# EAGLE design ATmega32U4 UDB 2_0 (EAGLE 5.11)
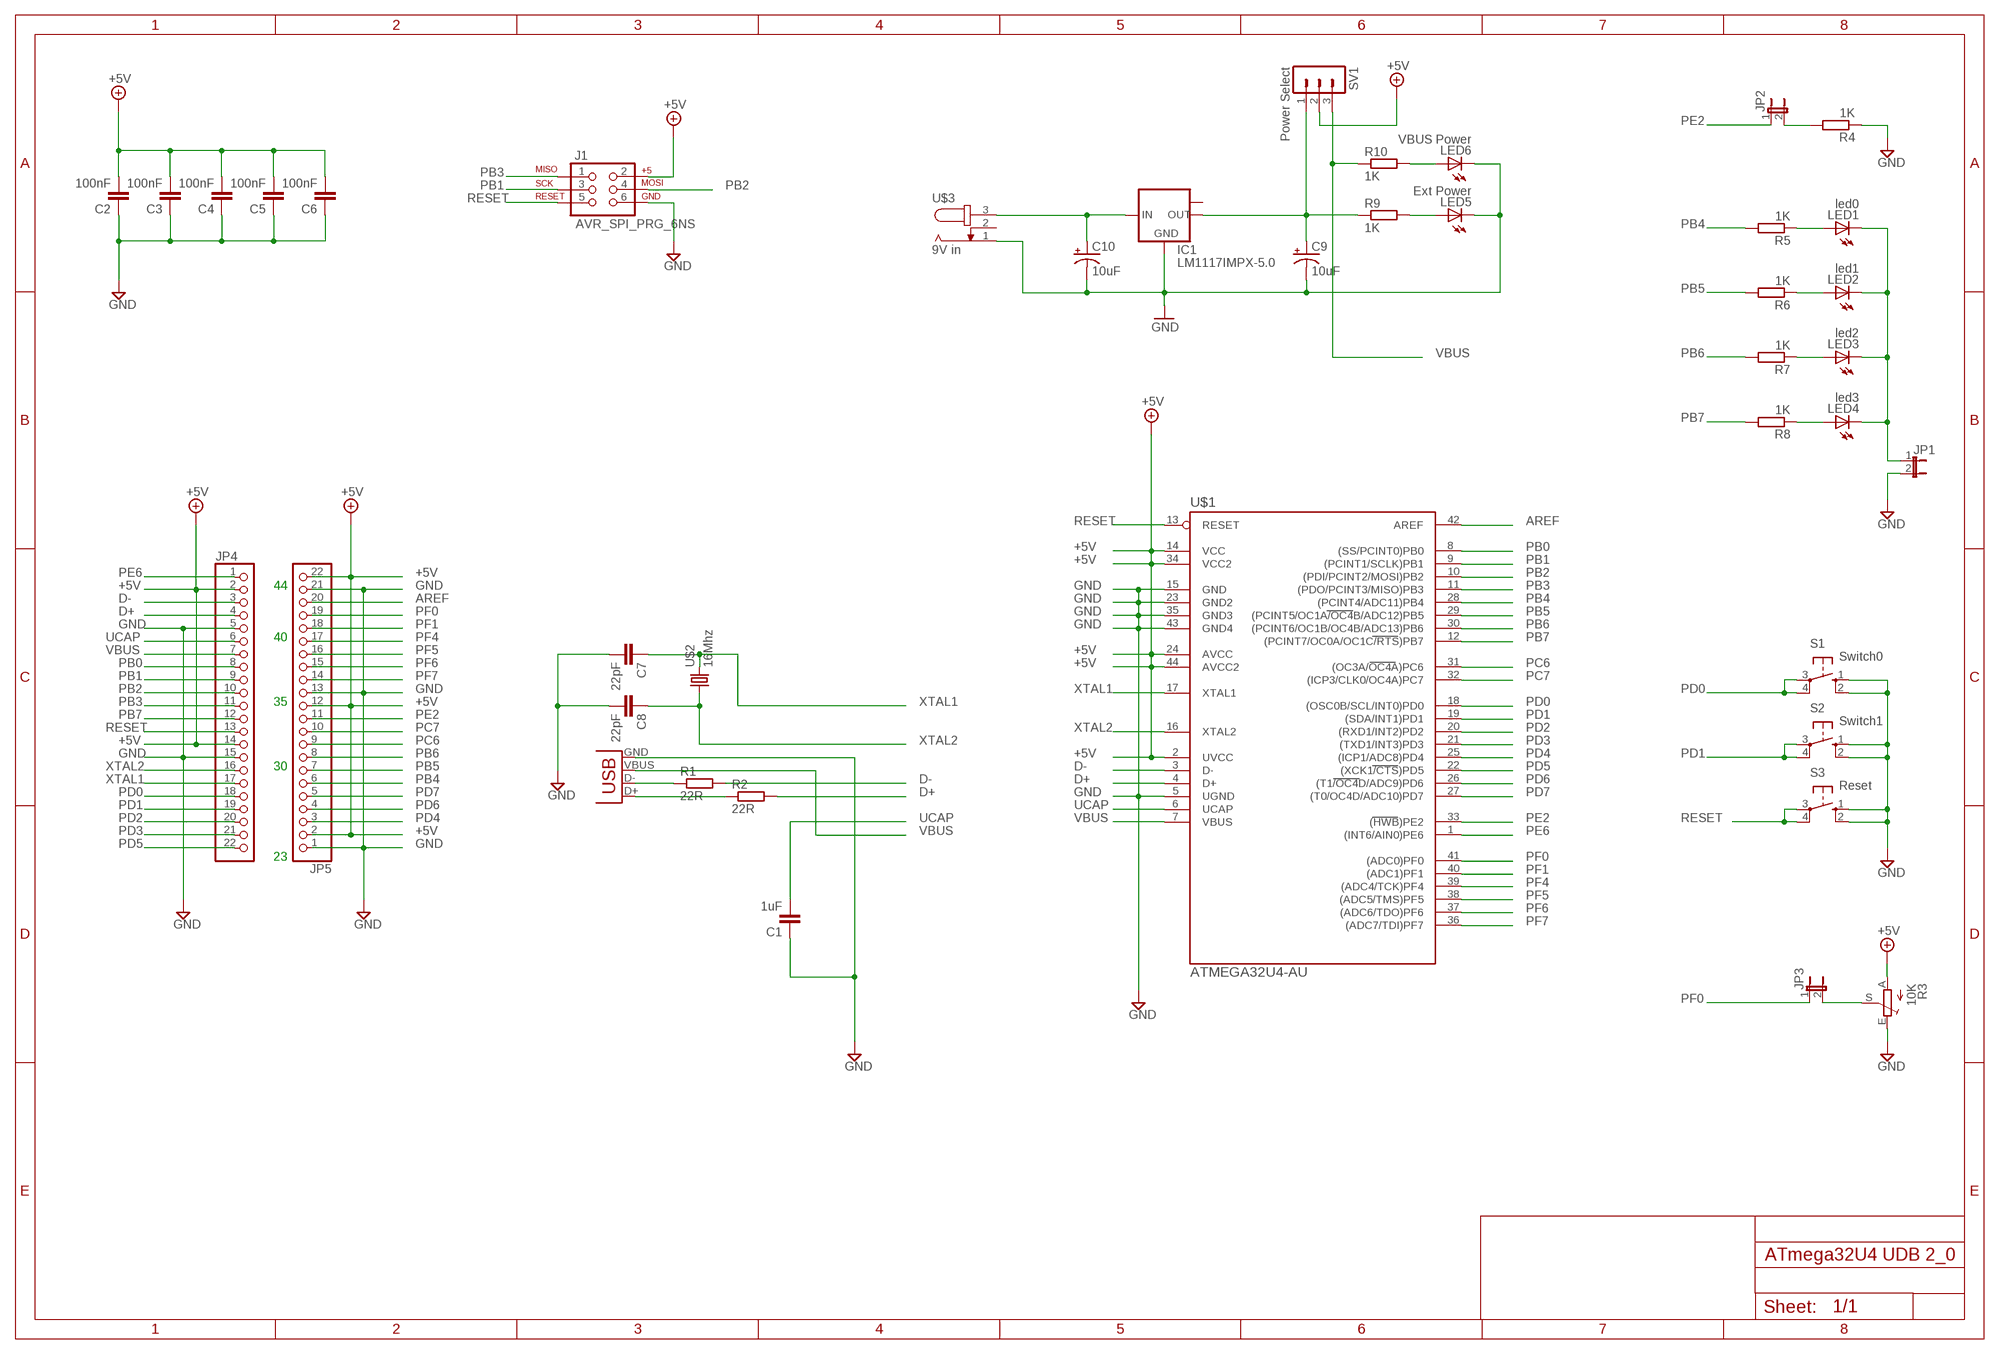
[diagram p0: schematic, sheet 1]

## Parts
C1  1uF  C-EUC0805  [C0805]
C2  100nF  C-EUC0805  [C0805]
C3  100nF  C-EUC0805  [C0805]
C4  100nF  C-EUC0805  [C0805]
C5  100nF  C-EUC0805  [C0805]
C6  100nF  C-EUC0805  [C0805]
C7  22pF  C-EUC0805  [C0805]
C8  22pF  C-EUC0805  [C0805]
C9  10uF  CAP_POL7343  [EIA7343]
C10  10uF  CAP_POL7343  [EIA7343]
IC1  LM1117IMPX-5.0  [SOT223]
J1  AVR_SPI_PRG_6NS  [2X3-NS]
JP1  JUMPER-2PTH  [1X02]
JP2  JUMPER-2PTH  [1X02]
JP3  JUMPER-2PTH  [1X02]
JP4  PINHD-1X22  [1X22]
JP5  PINHD-1X22  [1X22]
LED1  led0  LEDCHIPLED_0805  [CHIPLED_0805]
LED2  led1  LEDCHIPLED_0805  [CHIPLED_0805]
LED3  led2  LEDCHIPLED_0805  [CHIPLED_0805]
LED4  led3  LEDCHIPLED_0805  [CHIPLED_0805]
LED5  Ext Power  LEDCHIPLED_0805  [CHIPLED_0805]
LED6  VBUS Power  LEDCHIPLED_0805  [CHIPLED_0805]
R1  22R  R-EU_M1206  [M1206]
R2  22R  R-EU_M1206  [M1206]
R3  10K  TRIM_EU-CA9V  [CA9V]
R4  1K  R-EU_M1206  [M1206]
R5  1K  R-EU_M1206  [M1206]
R6  1K  R-EU_M1206  [M1206]
R7  1K  R-EU_M1206  [M1206]
R8  1K  R-EU_M1206  [M1206]
R9  1K  R-EU_M1206  [M1206]
R10  1K  R-EU_M1206  [M1206]
S1  Switch0  10-XX  [B3F-10XX]
S2  Switch1  10-XX  [B3F-10XX]
S3  Reset  10-XX  [B3F-10XX]
SV1  Power Select  MA03-1  [MA03-1]
U$1  ATMEGA32U4-AU  [TQFP44]
U$2  16Mhz  CRYSTAL_SMD3X5MM  [CRYSTAL_SMD_3X5MM]
U$3  9V in  DC_JACK  [DC_JACK]
X1  USBPTH  [USB-B-PTH]

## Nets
+5V: C2.2 C3.2 C4.2 C5.2 C6.2 J1.2 JP4.2 JP4.14 JP5.2 JP5.12 JP5.22 R3.A SV1.2 U$1.2(UVCC) U$1.14(VCC) U$1.24(AVCC) U$1.34(VCC2) U$1.44(AVCC2)
AREF: JP5.20 U$1.42(AREF)
D+: JP4.4 R2.2 U$1.4(D+)
D-: JP4.3 R1.2 U$1.3(D-)
GND: C1.1 C2.1 C3.1 C4.1 C5.1 C6.1 C7.2 C8.2 C9.C(-) C10.C(-) IC1.1(GND) J1.6 JP1.2 JP4.5 JP4.15 JP5.1 JP5.13 JP5.21 LED5.C LED6.C R3.E R4.1 S1.1(S) S1.2(S1) S2.1(S) S2.2(S1) S3.1(S) S3.2(S1) U$1.5(UGND) U$1.15(GND) U$1.23(GND2) U$1.35(GND3) U$1.43(GND4) U$3.1 X1.GND
N$2: R1.1 X1.D-
N$3: R2.1 X1.D+
N$5: JP2.2 R4.2
N$6: JP3.2 R3.S
N$8: C10.A(+) IC1.3(IN) U$3.3
N$10: C9.A(+) IC1.2(OUT) R9.1 SV1.1
N$13: LED6.A R10.2
N$16: JP1.1 LED1.C LED2.C LED3.C LED4.C
N$17: LED1.A R5.1
N$18: LED2.A R6.1
N$19: LED5.A R9.2
N$20: LED3.A R7.1
N$21: LED4.A R8.1
PB0: JP4.8 U$1.8((SS/PCINT0)PB0)
PB1: J1.3 JP4.9 U$1.9((PCINT1/SCLK)PB1)
PB2: J1.4 JP4.10 U$1.10((PDI/PCINT2/MOSI)PB2)
PB3: J1.1 JP4.11 U$1.11((PDO/PCINT3/MISO)PB3)
PB4: JP5.6 R5.2 U$1.28((PCINT4/ADC11)PB4)
PB5: JP5.7 R6.2 U$1.29((PCINT5/OC1A/OC4B/ADC12)PB5)
PB6: JP5.8 R7.2 U$1.30((PCINT6/OC1B/OC4B/ADC13)PB6)
PB7: JP4.12 R8.2 U$1.12((PCINT7/OC0A/OC1C/RTS)PB7)
PC6: JP5.9 U$1.31((OC3A/OC4A)PC6)
PC7: JP5.10 U$1.32((ICP3/CLK0/OC4A)PC7)
PD0: JP4.18 S1.3(P) S1.4(P1) U$1.18((OSC0B/SCL/INT0)PD0)
PD1: JP4.19 S2.3(P) S2.4(P1) U$1.19((SDA/INT1)PD1)
PD2: JP4.20 U$1.20((RXD1/INT2)PD2)
PD3: JP4.21 U$1.21((TXD1/INT3)PD3)
PD4: JP5.3 U$1.25((ICP1/ADC8)PD4)
PD5: JP4.22 U$1.22((XCK1/CTS)PD5)
PD6: JP5.4 U$1.26((T1/OC4D/ADC9)PD6)
PD7: JP5.5 U$1.27((T0/OC4D/ADC10)PD7)
PE2: JP2.1 JP5.11 U$1.33((HWB)PE2)
PE6: JP4.1 U$1.1((INT6/AIN0)PE6)
PF0: JP3.1 JP5.19 U$1.41((ADC0)PF0)
PF1: JP5.18 U$1.40((ADC1)PF1)
PF4: JP5.17 U$1.39((ADC4/TCK)PF4)
PF5: JP5.16 U$1.38((ADC5/TMS)PF5)
PF6: JP5.15 U$1.37((ADC6/TDO)PF6)
PF7: JP5.14 U$1.36((ADC7/TDI)PF7)
RESET: J1.5 JP4.13 S3.3(P) S3.4(P1) U$1.13(RESET)
UCAP: C1.2 JP4.6 U$1.6(UCAP)
VBUS: JP4.7 R10.1 SV1.3 U$1.7(VBUS) X1.VBUS
XTAL1: C7.1 JP4.17 U$1.17(XTAL1) U$2.2
XTAL2: C8.1 JP4.16 U$1.16(XTAL2) U$2.1
Unconnected: IC1.TAB(OUT1) U$3.2

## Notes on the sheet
- 44
- 40
- 35
- 30
- 23

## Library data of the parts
C1-C8 = rcl:C-EU: CAPACITOR, European symbol
C9 C10 = SparkFun:CAP_POL: Capacitor Polarized
IC1 = lm1117:LM1117IMPX-*
J1 = SparkFun:AVR_SPI_PRG_6: AVR ISP 6 Pin This is the reduced ISP connector for AVR programming. Common on Arduino. This footprint will take up less PCB space and can be used with a 10-pin to 6-pin adapter such as SKU: BOB-08508
JP1-JP3 = SparkFun:JUMPER-2: Jumper
JP4 JP5 = pinhead:PINHD-1X22: PIN HEADER
LED1-LED6 = led:LED: LED
R1 R2 R4-R10 = rcl:R-EU_: RESISTOR, European symbol
R3 = pot:TRIM_EU-: POTENTIOMETER
S1-S3 = switch-omron:10-XX: OMRON SWITCH; MPN: B3F-1000; OC_FARNELL: 176432; OC_NEWARK: 36M3542
SV1 = con-lstb:MA03-1: PIN HEADER; OC_FARNELL: unknown; OC_NEWARK: unknown
U$1 = mega32U4:ATMEGA32U4-AU
U$2 = simonslbr:CRYSTAL_SMD3X5MM: SMD Crystal 3.2mm X 5mm dual pads
U$3 = simonslbr:DC_JACK: DC Jack with wider pads for easier soldering
X1 = SparkFun:USB: USB Connectors USB-B-PTH is fully proven SKU : PRT-00139 USB-miniB is fully proven SKU : PRT-00587 USB-A-PCB is untested. USB-A-H is throughly reviewed, but untested. Spark Fun Electronics SKU : PRT-00437 USB-B-SMT is throughly reviewed, but untested. Needs silkscreen touching up. USB-A-S has not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

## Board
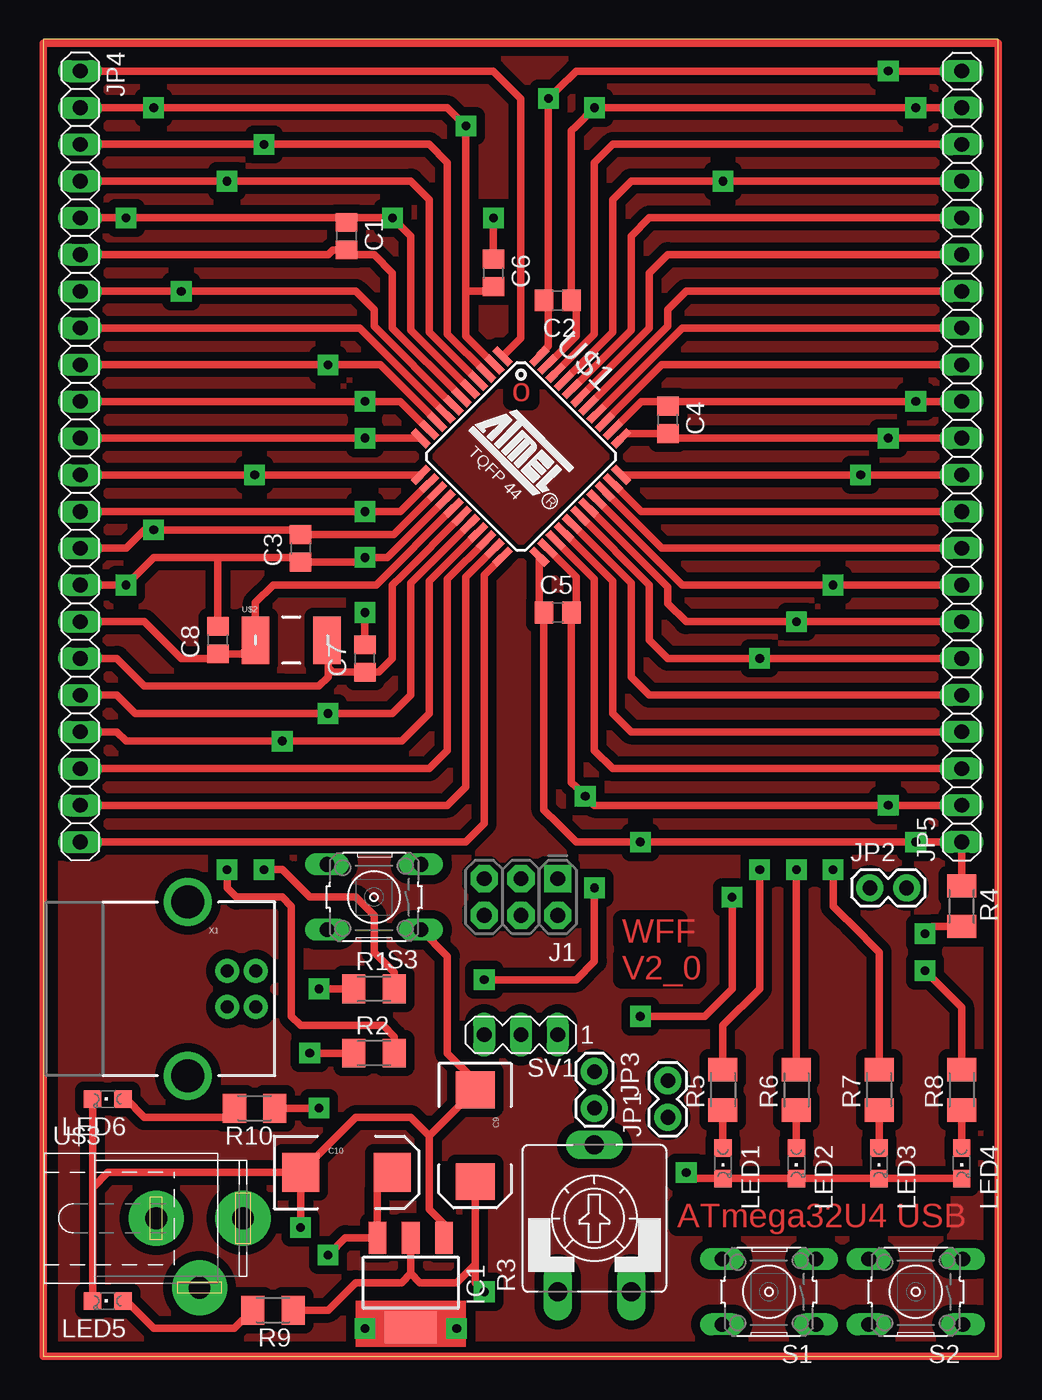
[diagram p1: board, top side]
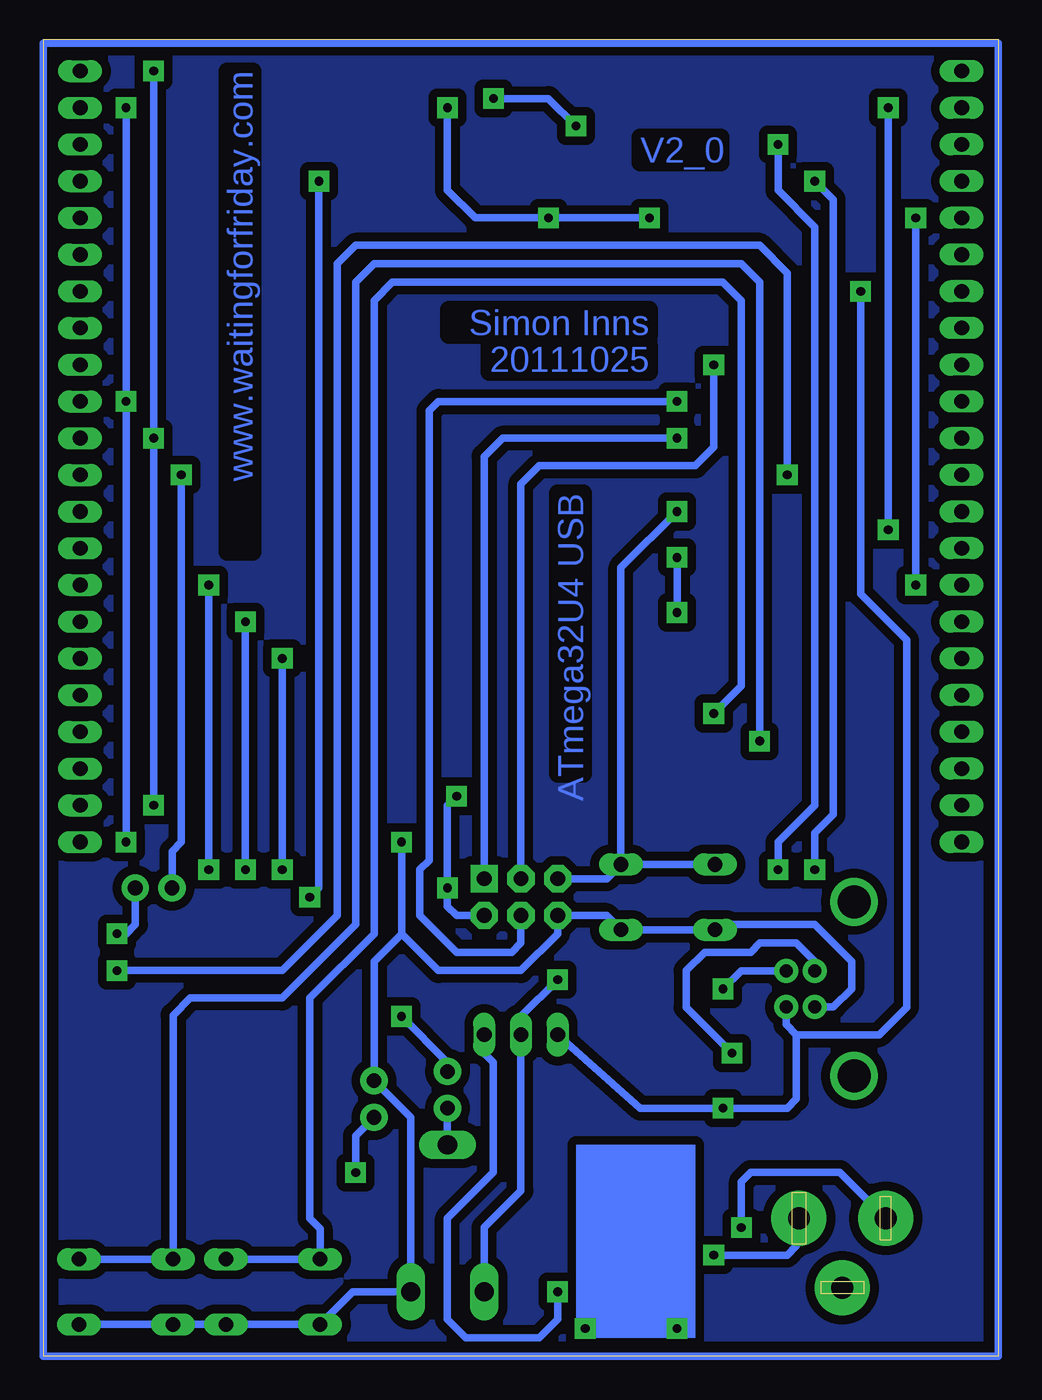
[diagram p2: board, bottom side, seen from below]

Size 66.02 x 91.11 mm. Coordinates in mm from the lower left corner, seen from the top.
Outline: 0,0 66.02,0 66.02,91.11 0,91.11 0,0
Copper layers (1*16): Top 0.035mm / dielectric 1.5mm / Bottom 0.035mm
Design rules "default": minimum track width 10mil, minimum drill 24mil, track to track 8mil, track to pad 8mil, pad to pad 8mil, via to via 8mil, smd to smd 8mil, copper to edge 40mil, drill to drill 8mil, minimum pad ring 10mil, minimum via ring 8mil, stop-mask expansion 4mil, vias tented up to drill 0mil, thermal gap 10mil

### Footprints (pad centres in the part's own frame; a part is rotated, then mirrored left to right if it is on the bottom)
C0805 = smd 1.3 x 1.5: 1 -0.95,0; 2 0.95,0
EIA7343 = smd 2.55 x 2.7: A 3.17,0; C -3.17,0
SOT223 = smd 1.219 x 2.235: 1 -2.311,-3.099; 2 0,-3.099; 3 2.311,-3.099 | smd 3.6 x 2.2: TAB 0,3.099
2X3-NS = drill 1.016 pad 1.88 square: 1 -2.54,-1.27 | drill 1.016 pad 1.88 octagon: 2 -2.54,1.27; 3 0,-1.27; 4 0,1.27; 5 2.54,-1.27; 6 2.54,1.27
1X02 = drill 1.016 pad 1.88 round: 1 0,0; 2 2.54,0
1X22 = drill 1.016 long: 1 -26.67,0; 2 -24.13,0; 3 -21.59,0; 4 -19.05,0; 5 -16.51,0; 6 -13.97,0; 7 -11.43,0; 8 -8.89,0; 9 -6.35,0; 10 -3.81,0; 11 -1.27,0; 12 1.27,0; 13 3.81,0; 14 6.35,0; 15 8.89,0; 16 11.43,0; 17 13.97,0; 18 16.51,0; 19 19.05,0; 20 21.59,0; 21 24.13,0; 22 26.67,0
CHIPLED_0805 = smd 1.2 x 1.2: A 0,-1.05; C 0,1.05
M1206 = smd 1.6 x 2: 1 -1.4,0; 2 1.4,0
CA9V = drill 1.321 long: A -2.54,-5.08; E 2.54,-5.08; S 0,5.08
B3F-10XX = drill 1.016 long: 1 -3.251,2.261; 2 3.251,2.261; 3 -3.251,-2.261; 4 3.251,-2.261
MA03-1 = drill 1.016 long: 1 -2.54,0; 2 0,0; 3 2.54,0
TQFP44 = smd 1.5 x 0.5: 1 -5.8,4; 2 -5.8,3.2; 3 -5.8,2.4; 4 -5.8,1.6; 5 -5.8,0.8; 6 -5.8,0; 7 -5.8,-0.8; 8 -5.8,-1.6; 9 -5.8,-2.4; 10 -5.8,-3.2; 11 -5.8,-4; 23 5.8,-4; 24 5.8,-3.2; 25 5.8,-2.4; 26 5.8,-1.6; 27 5.8,-0.8; 28 5.8,0; 29 5.8,0.8; 30 5.8,1.6; 31 5.8,2.4; 32 5.8,3.2; 33 5.8,4 | smd 0.5 x 1.5: 12 -4,-5.8; 13 -3.2,-5.8; 14 -2.4,-5.8; 15 -1.6,-5.8; 16 -0.8,-5.8; 17 0,-5.8; 18 0.8,-5.8; 19 1.6,-5.8; 20 2.4,-5.8; 21 3.2,-5.8; 22 4,-5.8; 34 4,5.8; 35 3.2,5.8; 36 2.4,5.8; 37 1.6,5.8; 38 0.8,5.8; 39 0,5.8; 40 -0.8,5.8; 41 -1.6,5.8; 42 -2.4,5.8; 43 -3.2,5.8; 44 -4,5.8
CRYSTAL_SMD_3X5MM = smd 1.9 x 3.302: 1 -2.485,-0.007; 2 2.468,-0.007
DC_JACK = drill 1.5 pad 3.81 round: 1 -0.46,0; 2 2.54,-4.8; 3 5.54,0
USB-B-PTH = drill 0.914 pad 1.676 round: D+ 0,1.25; D- 1.981,1.25; GND 0,-1.25; VBUS 1.981,-1.25 | drill 2.286 round: S1 -2.718,-6.02; S2 -2.718,6.02

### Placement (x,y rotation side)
C1  20.95,77.47 270 top
C2  35.56,73.03 180 top
C3  17.78,55.88 90 top
C4  43.18,64.77 270 top
C5  35.56,51.44 0 top
C6  31.11,74.93 270 top
C7  22.23,48.26 90 top
C8  12.06,49.53 90 top
C9  29.84,15.24 270 top
C10  20.95,12.7 0 top
IC1  25.4,5.08 180 top
J1  33.02,31.75 180 top
JP1  43.18,16.51 90 top
JP2  57.15,32.38 0 top
JP3  38.1,19.68 270 top
JP4  2.54,62.23 270 top
JP5  63.5,62.23 90 top
LED1  46.99,13.34 180 top
LED2  52.07,13.34 180 top
LED3  57.78,13.34 180 top
LED4  63.5,13.34 180 top
LED5  4.45,3.81 90 top
LED6  4.45,17.78 90 top
R1  22.86,25.4 0 top
R2  22.86,20.95 0 top
R3  38.1,9.53 0 top
R4  63.5,31.11 270 top
R5  46.99,18.41 90 top
R6  52.07,18.41 90 top
R7  57.78,18.41 90 top
R8  63.5,18.41 90 top
R9  15.88,3.17 180 top
R10  14.61,17.14 180 top
S1  50.16,4.45 180 top
S2  60.33,4.45 180 top
S3  22.86,31.75 180 top
SV1  33.02,22.23 180 top
U$1  33.02,62.23 315 top
U$2  17.14,49.53 0 top
U$3  8.26,9.53 0 top
X1  12.7,25.4 0 top

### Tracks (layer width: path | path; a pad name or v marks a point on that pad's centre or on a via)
+5V  (via drill 0.6 pad 1.42)
  Top 0.508: U$1.2 29.21,70.56 29.21,73.66 | 29.21,73.66 v29.21,85.09 27.94,86.36 v7.62,86.36 JP4.2 | JP5.22 v58.42,88.9 36.83,88.9 35.56,87.63 v34.92,87 34.92,73.34 C2.2 34.92,72.71 34.92,69.85 34.29,69.22 U$1.44 | U$1.34 40.27,63.82 C4.2 43.5,63.5 v58.42,63.5 JP5.12 | U$1.24 36.83,53.89 36.83,51.76 C5.2 36.51,39.69 36.83,39.37 v37.47,38.73 38.1,38.1 v58.42,38.1 JP5.2 | U$1.14 24.55,57.15 24.23,56.83 C3.2 17.46,57.15 v7.62,57.15 6.99,57.15 5.71,55.88 JP4.14 | C6.2 30.8,73.66 29.21,73.66 | v30.48,26.04 36.83,26.04 38.1,27.3 v38.1,32.38
  Bottom 0.508: v7.62,86.36 v7.62,57.15 | v58.42,88.9 v58.42,63.5 v58.42,38.1 | J1.2 37.47,30.48 38.1,31.11 v38.1,32.38 | v38.1,32.38 38.1,33.02 | 38.1,33.02 38.1,38.1 v37.47,38.73 | R3.A 35.56,8.89 33.02,11.43 33.02,20.95 SV1.2 33.02,23.5 v30.48,26.04 | v38.1,32.38 38.1,33.02 | v29.21,85.09 31.11,87 v34.92,87
AREF
  Top 0.508: U$1.42 38.1,70.7 38.1,82.55 39.37,83.82 JP5.20
D+  (via drill 0.6 pad 1.42)
  Top 0.508: U$1.4 26.67,70.84 26.67,80.01 25.4,81.28 v12.7,81.28 JP4.4 | R2.2 24.26,22.09 23.5,22.86 17.78,22.86 17.14,23.5 17.14,31.11 16.51,31.75 13.34,31.75 12.7,32.38 v12.7,33.66
  Bottom 0.508: v12.7,33.66 12.7,36.2 11.43,37.47 11.43,80.01 v12.7,81.28
D-  (via drill 0.6 pad 1.42)
  Top 0.508: U$1.3 27.94,70.7 27.94,82.55 26.67,83.82 v15.24,83.82 JP4.3 | R1.2 24.26,26.54 22.86,27.94 22.86,30.48 21.59,31.75 18.41,31.75 16.51,33.66 v15.24,33.66
  Bottom 0.508: v15.24,33.66 15.24,35.56 12.7,38.1 12.7,78.11 15.24,80.64 v15.24,83.82
GND  (via drill 0.6 pad 1.42)
  Top 0.508: U$1.5 25.4,70.98 25.4,71.12 25.4,77.47 v24.13,78.74 21.27,78.74 C1.1 20.64,78.74 JP4.5 v5.71,78.74 | U$1.43 36.83,70.57 36.83,72.7 C2.1 36.51,84.77 36.83,85.09 v38.1,86.36 v60.33,86.36 JP5.21 | U$1.35 41.35,66.04 42.55,66.04 42.87,65.72 C4.1 43.5,66.04 v60.33,66.04 JP5.13 | U$1.15 23.77,55.24 v22.23,55.24 21.91,54.93 C3.1 17.46,55.24 12.06,55.24 | JP4.15 v5.71,53.34 7.62,55.24 10.16,55.24 12.06,55.24 | v22.23,51.44 C7.2 | U$1.23 34.29,51.75 C5.1 34.61,37.78 35.56,36.83 36.83,35.56 v41.27,35.56 v60.33,35.56 JP5.1 R4.1 | v31.11,78.74 C6.1 | 12.06,55.24 C8.2 | IC1.1 27.71,9.12 26.67,10.16 | 26.67,10.16 26.67,15.23 C9.C 29.84,19.05 27.94,20.95 27.94,27.66 S3.1 | C10.C v17.79,8.89 v17.78,8.89 | LED5.C 3.4,11.43 | 3.4,11.43 3.4,11.65 4.45,12.7 C10.C | 3.4,11.43 LED6.C | 26.67,15.24 26.67,10.16 | 26.67,15.24 C9.C | 26.67,15.24 26.67,10.16 | 26.67,15.24 25.4,16.51 21.59,16.51 C10.C
  Bottom 0.508: v22.23,55.24 v22.23,51.44 | v24.13,78.74 29.84,78.74 v31.11,78.74 36.2,78.74 38.1,80.64 v38.1,86.36 | v60.33,86.36 v60.33,66.04 v60.33,35.56 | v5.71,78.74 v5.71,53.34 | 41.27,29.21 38.73,26.67 33.02,26.67 30.48,29.21 J1.6 27.1,30.48 S3.1 S3.2 19.25,29.84 12.7,29.84 10.16,27.3 10.16,25.4 11.41,24.15 X1.GND | 41.27,29.21 v41.27,35.56 | S2.1 S2.2 S1.1 S1.2 44.65,4.45 R3.E 40.64,16.51 JP1.2 43.18,27.3 41.27,29.21 | v17.78,8.89 17.78,12.06 17.14,12.7 10.97,12.7 U$3.1
N$1
  Bottom 0.508: 0,90.81 66.04,90.81 66.04,0 0,0 0,90.81
N$2  (via drill 0.6 pad 1.42)
  Top 0.508: v19.05,25.4 R1.1
  Bottom 0.508: X1.D- 17.8,26.65 v19.05,25.4
N$3  (via drill 0.6 pad 1.42)
  Top 0.508: v18.41,20.95 R2.1
  Bottom 0.508: X1.D+ 12.7,27.3 13.97,28.57 16.51,28.57 17.14,27.94 20.32,27.94 21.59,26.67 21.59,24.13 v18.41,20.95
N$4
  pour Top (isolate 0.61): 0,90.81 66.04,90.81 66.04,0 0,0
N$5  (via drill 0.6 pad 1.42)
  Top 0.508: 60.83,29.34 v60.96,29.21 61.47,29.71 R4.2
  Bottom 0.508: v60.96,29.21 60.33,29.21 59.69,29.84 JP2.2
N$6
  Bottom 0.508: R3.S JP3.2
N$7
  Top 0.508: 0,90.81 66.04,90.81 66.04,0 0,0 0,90.81
N$8  (via drill 0.6 pad 1.42)
  Top 0.508: C10.A 23.09,11.66 IC1.3 20.88,8.18 v19.68,6.99
  Bottom 0.508: v19.68,6.99 14.61,6.99 13.97,7.62 13.97,9.35 U$3.3
N$9
  pour Bottom (isolate 0.61): 0,90.81 66.04,90.81 66.04,0 0,0
N$10  (via drill 0.6 pad 1.42)
  Top 0.508: R9.1 19.68,3.17 21.59,5.08 24.77,5.08 25.4,5.71 | 25.4,5.71 IC1.2 | 25.4,5.71 26.04,5.08 28.57,5.08 29.84,6.35 C9.A 29.84,5.08 v30.48,4.45
  Bottom 0.508: v30.48,4.45 30.48,2.54 31.75,1.27 36.83,1.27 38.1,2.54 38.1,9.53 34.92,12.7 34.92,20.32 35.56,20.95 SV1.1
N$11  (via drill 0.6 pad 1.42)
  other vias: 22.23,1.91
N$12  (via drill 0.6 pad 1.42)
  other vias: 28.57,1.91
N$13
  Top 0.508: LED6.A 5.71,17.78 6.99,16.51 12.57,16.51 R10.2
N$16  (via drill 0.6 pad 1.42)
  Top 0.508: LED4.C LED3.C LED2.C LED1.C 44.87,12.29 v44.45,12.7
  Bottom 0.508: v44.45,12.7 44.45,15.24 JP1.1
N$17
  Top 0.508: LED1.A R5.1
N$18
  Top 0.508: LED2.A R6.1
N$19
  Top 0.508: LED5.A 5.71,3.81 7.62,1.91 13.21,1.91 R9.2
N$20
  Top 0.508: LED3.A R7.1
N$21
  Top 0.508: LED4.A R8.1
PB0
  Top 0.508: U$1.8 21.87,71.12 JP4.8
PB1  (via drill 0.6 pad 1.42)
  Top 0.508: U$1.9 23.28,68.58 v19.68,68.58 JP4.9
  Bottom 0.508: J1.3 33.02,60.33 31.75,61.59 20.95,61.59 19.68,62.87 v19.68,68.58
PB2  (via drill 0.6 pad 1.42)
  Top 0.508: U$1.10 24.68,66.04 23.5,66.04 | v22.23,66.04 JP4.10 | v22.23,66.04 23.5,66.04 | v22.23,66.04 23.5,66.04
  Bottom 0.508: J1.4 33.02,28.57 33.66,27.94 37.47,27.94 40.01,30.48 40.01,33.66 39.37,34.29 39.37,65.41 38.73,66.04 23.5,66.04 v22.23,66.04
PB3  (via drill 0.6 pad 1.42)
  Top 0.508: U$1.11 v22.23,63.5 JP4.11
  Bottom 0.508: J1.1 35.56,62.23 34.29,63.5 24.13,63.5 v22.23,63.5
PB4  (via drill 0.6 pad 1.42)
  Top 0.508: U$1.28 41.91,53.34 41.91,49.53 43.18,48.26 v49.53,48.26 JP5.6 | R5.2 46.99,22.86 49.53,25.4 v49.53,33.66
  Bottom 0.508: v49.53,33.66 v49.53,48.26
PB5  (via drill 0.6 pad 1.42)
  Top 0.508: U$1.29 43.18,53.2 43.18,52.07 44.45,50.8 v52.07,50.8 JP5.7 | R6.2 v52.07,33.66
  Bottom 0.508: v52.07,33.66 v52.07,50.8
PB6  (via drill 0.6 pad 1.42)
  Top 0.508: U$1.30 44.17,53.34 v54.61,53.34 JP5.8 | R7.2 57.78,27.94 55.88,29.84 55.24,30.48 54.61,31.11 v54.61,33.66
  Bottom 0.508: v54.61,33.66 v54.61,53.34
PB7  (via drill 0.6 pad 1.42)
  Top 0.508: U$1.12 v14.61,60.96 JP4.12 | R8.2 63.5,24.13 v60.96,26.67
  Bottom 0.508: v60.96,26.67 49.53,26.67 45.72,30.48 45.72,75.56 44.45,76.83 16.51,76.83 14.61,74.93 v14.61,60.96
PC6
  Top 0.508: U$1.31 42.76,55.88 JP5.9
PC7
  Top 0.508: U$1.32 41.35,58.42 JP5.10
PD0  (via drill 0.6 pad 1.42)
  Top 0.508: U$1.18 25.4,53.48 25.4,45.72 24.13,44.45 19.05,44.45 | 19.05,44.45 6.35,44.45 5.08,45.72 JP4.18 | 19.05,44.45 v19.68,44.45
  Bottom 0.508: v19.68,44.45 17.78,46.35 17.78,73.03 19.05,74.3 41.91,74.3 43.18,73.03 43.18,29.21 47.62,24.77 47.62,20.32 47.62,9.53 46.91,8.81 S1.4 S1.3
PD1  (via drill 0.6 pad 1.42)
  Top 0.508: U$1.19 26.67,53.62 26.67,44.45 24.77,42.55 15.88,42.55 | 15.88,42.55 v16.51,42.55 | 15.88,42.55 5.71,42.55 5.08,43.18 JP4.19
  Bottom 0.508: v16.51,42.55 16.51,74.3 17.78,75.56 43.18,75.56 44.45,74.3 44.45,29.84 49.53,24.77 55.88,24.77 57.07,23.57 S2.4 S2.3
PD2
  Top 0.508: U$1.20 27.94,53.76 27.94,41.91 26.67,40.64 JP4.20
PD3
  Top 0.508: U$1.21 29.21,53.9 29.21,39.37 27.94,38.1 JP4.21
PD4
  Top 0.508: U$1.25 38.1,53.76 38.1,41.91 39.37,40.64 JP5.3
PD5
  Top 0.508: U$1.22 30.48,54.03 30.48,36.83 29.21,35.56 JP4.22
PD6
  Top 0.508: U$1.26 39.37,53.62 39.37,44.45 40.64,43.18 JP5.4
PD7
  Top 0.508: U$1.27 40.64,53.48 40.64,46.99 41.91,45.72 JP5.5
PE2  (via drill 0.6 pad 1.42)
  Top 0.508: U$1.33 v56.52,60.96 JP5.11
  Bottom 0.508: JP2.1 57.15,34.92 56.52,35.56 v56.52,60.96
PE6
  Top 0.508: U$1.1 33.02,70.43 33.02,71.75 33.02,87 31.11,88.9 JP4.1
PF0  (via drill 0.6 pad 1.42)
  Top 0.508: U$1.41 39.37,70.84 39.37,80.01 40.64,81.28 v46.99,81.28 JP5.19 | v41.27,23.5 45.72,23.5 47.62,25.4 v47.62,31.75
  Bottom 0.508: JP3.1 38.1,20.32 v41.27,23.5 | v47.62,31.75 46.99,32.38 v46.99,81.28
PF1
  Top 0.508: U$1.40 40.64,70.98 40.64,77.47 41.91,78.74 JP5.18
PF4
  Top 0.508: U$1.39 41.91,71.12 41.91,74.93 43.18,76.2 JP5.17
PF5
  Top 0.508: U$1.38 43.18,71.26 43.18,72.39 44.45,73.66 JP5.16
PF6
  Top 0.508: U$1.37 44.17,71.12 JP5.15
PF7
  Top 0.508: U$1.36 42.76,68.58 JP5.14
RESET  (via drill 0.6 pad 1.42)
  Top 0.508: U$1.13 24.68,58.42 v22.23,58.42 JP4.13
  Bottom 0.508: J1.5 27.1,33.02 S3.3 | 26.04,54.61 v22.23,58.42 | 26.11,54.53 26.04,54.61 | S3.4 S3.3 | S3.3 26.11,54.53 | 26.11,54.53 26.04,54.61
UCAP
  Top 0.508: U$1.6 24.13,71.12 24.13,74.93 22.86,76.2 21.27,76.2 C1.2 20,76.52 19.68,76.2 JP4.6
VBUS  (via drill 0.6 pad 1.42)
  Top 0.508: U$1.7 22.86,71.26 22.86,72.39 21.59,73.66 v9.53,73.66 JP4.7 | v19.05,17.14 R10.1
  Bottom 0.508: X1.VBUS 14.68,22.94 13.97,22.23 | 13.97,22.23 8.26,22.23 6.35,24.13 6.35,49.53 9.53,52.7 v9.53,73.66 | SV1.3 24.77,17.14 v19.05,17.14 14.61,17.14 13.97,17.78 13.97,22.23
XTAL1
  Top 0.508: U$1.17 24.77,53.98 24.13,53.34 24.13,48.26 23.18,47.31 C7.1 20,47.31 19.68,47.62 | JP4.17 5.08,48.26 6.99,46.35 16.51,46.35 19.05,46.35 19.68,46.99 19.68,47.62 | 19.68,47.62 19.68,48.18 U$2.2
XTAL2
  Top 0.508: U$1.16 23,53.34 15.88,53.34 14.66,52.12 U$2.1 13.72,48.58 C8.1 | C8.1 12.39,48.25 | C8.1 11.74,48.26 9.53,48.26 6.99,50.8 JP4.16
(copper drawn outside any net)
  shapes: Bottom area x1, Top area x1

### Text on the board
Top: o | WFF | V2_0 | ATmega32U4 USB
Bottom: www.waitingforfriday.com | V2_0 | Simon Inns | 20111025 | ATmega32U4 USB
